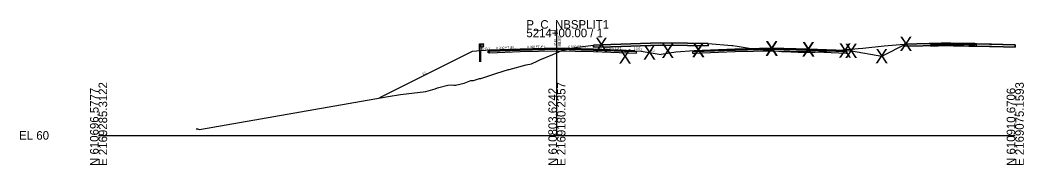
# Model space of a CAD drawing. Extents: x -26 to 1303, y -3010 to 12038.
# Drawn here: x 974.3 to 1302.8, y 7990.3 to 8037.8 of the extents above; entities that cross this region are included whole.
import ezdxf

# ---------------------------------------------------------------- set-up
doc = ezdxf.new("R2010")
doc.units = 0
for name, color, linetype in [('RD_GPK_XS_Cell', 7, 'Continuous'), ('RD_GPK_XS_Text_Node', 7, 'Continuous'), ('RD_PD_Final_TrvlWay', 7, 'Continuous'), ('RD_XS_Base', 7, 'Continuous'), ('RD_XS_ExGround', 7, 'Continuous'), ('RD_XS_ExPaveRet', 7, 'Continuous'), ('RD_XS_GR', 7, 'Continuous'), ('RD_XS_Greenside', 7, 'Continuous'), ('RD_XS_Pave', 7, 'Continuous'), ('RD_XS_PaveOvlay_CP', 7, 'Continuous'), ('RD_XS_TieSlope', 7, 'Continuous'), ('RD_XS_TX_Elev_EX', 7, 'Continuous'), ('RD_XS_TX_Elev_PR', 7, 'Continuous'), ('RD_XS_TX_ShdSlope', 7, 'Continuous'), ('RD_XS_TX_Slope', 7, 'Continuous')]:
    doc.layers.add(name, color=color, linetype=linetype)

msp = doc.modelspace()

# ---------------------------------------------------------------- linework, layer by layer
at = {"layer": 'RD_GPK_XS_Cell'}
for p, q in [((1150, 8000), (1150, 8035)), ((1000, 8000), (1150, 8000)), ((1150, 8000), (1300, 8000))]:
    msp.add_line(p, q, dxfattribs=at)
at = {"layer": 'RD_PD_Final_TrvlWay'}
for p, q in [((1125.11, 8027.7), (1124.61, 8027.66)), ((1124.61, 8027.66), (1124.61, 8024.09)), ((1125.11, 8024.09), (1125.11, 8027.7))]:
    msp.add_line(p, q, dxfattribs=at)
at = {"layer": 'RD_XS_Base'}
for p, q in [((1272.3, 8029.77), (1272.8, 8029.78)), ((1272.3, 8029.27), (1272.3, 8029.77)), ((1272.8, 8029.78), (1274.81, 8029.82)), ((1274.81, 8029.82), (1279.81, 8029.92)), ((1279.81, 8029.42), (1274.81, 8029.32)), ((1279.81, 8029.98), (1279.81, 8030.08)), ((1279.81, 8030.08), (1279.81, 8029.83)), ((1279.81, 8029.92), (1279.81, 8029.98)), ((1281.66, 8029.88), (1279.81, 8029.92)), ((1279.81, 8029.92), (1279.81, 8029.42)), ((1279.81, 8029.83), (1279.81, 8029.42)), ((1279.81, 8029.42), (1281.66, 8029.38)), ((1284.81, 8029.82), (1281.66, 8029.88)), ((1281.66, 8029.38), (1284.81, 8029.32)), ((1285.53, 8029.8), (1284.81, 8029.82)), ((1286.81, 8029.78), (1285.53, 8029.8)), ((1286.99, 8029.77), (1286.81, 8029.78)), ((1287.31, 8029.77), (1286.99, 8029.77)), ((1287.31, 8029.59), (1287.31, 8029.77)), ((1287.31, 8029.27), (1287.31, 8029.59)), ((1127.5, 8027.59), (1128, 8027.61)), ((1127.5, 8027.09), (1127.5, 8027.59)), ((1127.5, 8027.59), (1127.5, 8027.59)), ((1128, 8027.11), (1127.5, 8027.09)), ((1127.5, 8027.09), (1127.5, 8027.09)), ((1127.5, 8027.09), (1127.5, 8027.09)), ((1138, 8028.01), (1128, 8027.61)), ((1128, 8027.61), (1128, 8027.61)), ((1128, 8027.11), (1138, 8027.51)), ((1128, 8027.11), (1128, 8027.11)), ((1150, 8028.25), (1138, 8028.01)), ((1138, 8028.01), (1138, 8028.01)), ((1138, 8027.51), (1150, 8027.75)), ((1138, 8027.51), (1138, 8027.51)), ((1150, 8028.25), (1150, 8028.41)), ((1150, 8028.41), (1150, 8028.41)), ((1150, 8028.41), (1150, 8028.41)), ((1150, 8028.41), (1150, 8027.75)), ((1150, 8027.75), (1150, 8028.25)), ((1150, 8028.25), (1150, 8028.25)), ((1150, 8028.25), (1150, 8028.25)), ((1150, 8028.25), (1150, 8028.25)), ((1162, 8028.01), (1150, 8028.25)), ((1150, 8027.75), (1150, 8027.75)), ((1150, 8027.75), (1150, 8027.75)), ((1150, 8027.75), (1162, 8027.51)), ((1175.55, 8027.47), (1162, 8028.01)), ((1162, 8027.51), (1176.05, 8026.95)), ((1164, 8027.93), (1164, 8027.93)), ((1164, 8027.43), (1164, 8027.43)), ((1176.05, 8027.45), (1175.55, 8027.47)), ((1175.55, 8027.47), (1175.55, 8027.47)), ((1176.05, 8026.95), (1176.05, 8027.45)), ((1176.05, 8027.45), (1176.05, 8027.45)), ((1194.9, 8027.48), (1194.4, 8027.46)), ((1194.4, 8027.46), (1194.4, 8027.46)), ((1194.4, 8027.46), (1194.4, 8026.96)), ((1194.4, 8026.96), (1194.9, 8026.98)), ((1194.4, 8026.96), (1194.4, 8026.96)), ((1194.4, 8026.96), (1194.4, 8026.96)), ((1208.27, 8028.01), (1194.9, 8027.48)), ((1194.9, 8026.98), (1208.27, 8027.51)), ((1194.93, 8027.48), (1194.9, 8027.48)), ((1194.9, 8026.98), (1194.93, 8026.98)), ((1208.36, 8028.01), (1208.27, 8028.01)), ((1208.27, 8027.51), (1208.36, 8027.51)), ((1220.36, 8028.25), (1208.36, 8028.01)), ((1208.36, 8027.51), (1220.36, 8027.75)), ((1220.36, 8028.25), (1220.36, 8028.41)), ((1220.36, 8028.41), (1220.36, 8027.76)), ((1220.36, 8027.75), (1220.36, 8028.25)), ((1220.36, 8028.25), (1220.36, 8028.25)), ((1220.36, 8028.25), (1220.36, 8028.25)), ((1232.28, 8028.01), (1220.36, 8028.25)), ((1220.36, 8028.25), (1220.36, 8028.25)), ((1220.36, 8027.76), (1220.36, 8027.75)), ((1220.36, 8027.75), (1220.36, 8027.75)), ((1220.36, 8027.75), (1232.28, 8027.51)), ((1232.36, 8028.01), (1232.28, 8028.01)), ((1232.28, 8027.51), (1232.36, 8027.51)), ((1244.27, 8027.54), (1232.36, 8028.01)), ((1232.36, 8027.51), (1244.76, 8027.02)), ((1244.36, 8027.53), (1244.27, 8027.54)), ((1244.86, 8027.51), (1244.36, 8027.53)), ((1244.76, 8027.02), (1244.86, 8027.01)), ((1244.86, 8027.02), (1244.86, 8027.51)), ((1244.86, 8027.51), (1244.86, 8027.51)), ((1244.86, 8027.01), (1244.86, 8027.02)), ((1272.8, 8029.28), (1272.3, 8029.27)), ((1274.81, 8029.32), (1272.8, 8029.28)), ((1284.81, 8029.32), (1285.71, 8029.3)), ((1285.71, 8029.3), (1287.31, 8029.27))]:
    msp.add_line(p, q, dxfattribs=at)
at = {"layer": 'RD_XS_ExGround'}
msp.add_lwpolyline([(1031.91, 8002.12), (1032.33, 8002.12), (1033.07, 8001.92), (1094.8, 8012.79), (1098.76, 8013.47), (1107.09, 8014.38), (1110.17, 8015.26), (1110.96, 8015.57), (1114.35, 8016.51), (1115.54, 8016.57), (1116.29, 8016.51), (1116.83, 8016.47), (1119.67, 8017.18), (1121.83, 8018.02), (1122.67, 8018.01), (1124.65, 8018.63), (1125.12, 8018.66), (1130.36, 8020.45), (1134.15, 8021.57), (1134.18, 8021.58), (1134.2, 8021.58), (1134.37, 8021.63), (1139.93, 8023.19), (1141.71, 8023.52), (1143.58, 8024.4), (1144.42, 8024.79), (1148.61, 8026.5), (1151.61, 8027.86), (1156.64, 8028.98), (1161.99, 8029.65), (1167.6, 8029.84), (1183.9, 8030.39), (1192.72, 8030.24), (1199.5, 8030.11), (1207.23, 8029.53), (1207.57, 8029.5), (1209.03, 8029.28), (1213.59, 8028.52), (1217.46, 8028.12), (1222.49, 8027.64), (1223.49, 8027.53), (1224.26, 8027.49), (1228.91, 8027.34), (1233.06, 8027.15), (1247.46, 8028.41), (1248.58, 8028.5), (1250.13, 8028.66), (1257.05, 8029.33), (1263.62, 8029.98), (1275.72, 8030.21), (1278.6, 8030.26), (1291.59, 8029.91), (1300, 8029.67)], dxfattribs=at)
at = {"layer": 'RD_XS_ExPaveRet'}
for p, q in [((1167.6, 8029.84), (1161.99, 8029.65)), ((1183.9, 8030.39), (1167.6, 8029.84)), ((1192.72, 8030.24), (1183.9, 8030.39)), ((1278.93, 8030.26), (1278.6, 8030.26)), ((1300, 8029.67), (1300, 8028.92)), ((1300, 8028.92), (1300, 8029.67))]:
    msp.add_line(p, q, dxfattribs=at)
for points in [[(1199.5, 8030.11), (1199.5, 8029.36), (1199.5, 8029.36), (1199.5, 8029.36), (1192.72, 8029.49), (1192.72, 8029.49), (1183.9, 8029.64), (1183.9, 8029.64), (1183.9, 8029.64), (1167.6, 8029.09), (1167.6, 8029.09), (1161.99, 8028.9), (1161.99, 8028.9), (1161.99, 8028.9), (1161.99, 8029.65), (1161.99, 8029.65), (1167.6, 8029.84), (1167.6, 8029.84), (1183.9, 8030.39), (1183.9, 8030.39), (1183.9, 8030.39), (1192.72, 8030.24), (1192.72, 8030.24), (1199.5, 8030.11), (1199.5, 8030.11)], [(1161.99, 8029.65), (1161.99, 8028.9), (1167.6, 8029.09), (1183.9, 8029.64), (1192.72, 8029.49), (1199.5, 8029.36), (1199.5, 8029.36), (1199.5, 8030.11), (1199.5, 8030.11), (1192.72, 8030.24)], [(1300, 8028.92), (1292.21, 8029.14), (1291.59, 8029.16), (1278.93, 8029.51), (1278.6, 8029.51), (1275.98, 8029.46), (1275.72, 8029.46), (1263.89, 8029.23), (1263.62, 8029.23), (1263.62, 8029.23), (1263.62, 8029.23), (1263.62, 8029.25), (1263.62, 8029.98), (1263.62, 8029.98), (1263.62, 8029.98), (1263.89, 8029.98), (1275.72, 8030.21), (1275.98, 8030.21), (1278.6, 8030.26), (1278.93, 8030.26), (1291.59, 8029.91), (1292.21, 8029.89)], [(1278.6, 8030.26), (1275.98, 8030.21), (1275.72, 8030.21), (1263.89, 8029.98), (1263.62, 8029.98), (1263.62, 8029.98)], [(1263.62, 8029.98), (1263.62, 8029.25), (1263.62, 8029.23), (1263.62, 8029.23), (1263.89, 8029.23), (1275.72, 8029.46), (1275.98, 8029.46), (1278.6, 8029.51), (1278.93, 8029.51), (1291.59, 8029.16), (1292.21, 8029.14), (1300, 8028.92)], [(1300, 8029.67), (1292.21, 8029.89), (1291.59, 8029.91), (1278.93, 8030.26)], [(1292.21, 8029.89), (1300, 8029.67)]]:
    msp.add_lwpolyline(points, dxfattribs=at)
at = {"layer": 'RD_XS_GR'}
for points in [[(1125.11, 8030.09), (1125.11, 8027.7), (1124.61, 8027.66), (1124.61, 8030.09), (1124.86, 8030.09), (1125.11, 8030.09)], [(1125.77, 8030.09), (1125.77, 8028.93), (1125.11, 8028.93), (1125.11, 8030.09), (1125.77, 8030.09)], [(1126.04, 8029.8), (1125.77, 8030.09), (1125.77, 8028.93), (1125.77, 8028.93), (1125.77, 8028.93), (1126.04, 8029.22), (1126.04, 8029.22), (1125.77, 8029.51), (1125.77, 8029.51), (1126.04, 8029.8), (1126.04, 8029.8)]]:
    msp.add_lwpolyline(points, dxfattribs=at)
at = {"layer": 'RD_XS_Greenside'}
for p, q in [((1256.36, 8026.02), (1264.3, 8029.99)), ((1122.29, 8027.47), (1091.92, 8012.29)), ((1177.55, 8027.63), (1184.17, 8026.52)), ((1188.9, 8027.31), (1184.17, 8026.52)), ((1246.36, 8027.69), (1256.36, 8026.02))]:
    msp.add_line(p, q, dxfattribs=at)
at = {"layer": 'RD_XS_Pave'}
for p, q in [((1273.59, 8030.11), (1272.8, 8030.1)), ((1272.8, 8030.1), (1272.8, 8030)), ((1272.8, 8030), (1272.8, 8029.94)), ((1274.81, 8029.98), (1272.8, 8029.94)), ((1272.8, 8029.94), (1273.59, 8029.95)), ((1272.8, 8029.94), (1272.8, 8029.78)), ((1272.8, 8029.78), (1274.81, 8029.82)), ((1274.81, 8030.14), (1273.59, 8030.11)), ((1273.59, 8029.95), (1274.81, 8029.98)), ((1276.73, 8030.18), (1274.81, 8030.14)), ((1279.81, 8030.08), (1274.81, 8029.98)), ((1274.81, 8029.98), (1276.73, 8030.02)), ((1274.81, 8029.82), (1279.81, 8029.92)), ((1279.81, 8030.24), (1276.73, 8030.18)), ((1276.73, 8030.02), (1279.81, 8030.08)), ((1281.66, 8030.2), (1279.81, 8030.24)), ((1279.81, 8030.08), (1281.66, 8030.04)), ((1284.81, 8029.98), (1279.81, 8030.08)), ((1279.81, 8030.08), (1279.81, 8029.92)), ((1279.81, 8029.92), (1279.81, 8030.08)), ((1279.81, 8029.92), (1284.81, 8029.82)), ((1284.81, 8030.14), (1281.66, 8030.2)), ((1281.66, 8030.04), (1284.81, 8029.98)), ((1285.53, 8030.12), (1284.81, 8030.14)), ((1284.81, 8029.98), (1285.53, 8029.96)), ((1286.81, 8029.94), (1284.81, 8029.98)), ((1284.81, 8029.82), (1286.81, 8029.78)), ((1286.81, 8030.1), (1285.53, 8030.12)), ((1285.53, 8029.96), (1286.81, 8029.94)), ((1286.81, 8029.99), (1286.81, 8030.1)), ((1286.81, 8029.94), (1286.81, 8029.99)), ((1286.81, 8029.78), (1286.81, 8029.94)), ((1138, 8028.33), (1128, 8027.93)), ((1138, 8028.17), (1128, 8027.77)), ((1128, 8027.77), (1138, 8028.17)), ((1128, 8027.61), (1138, 8028.01)), ((1128, 8027.93), (1128, 8027.93)), ((1128, 8027.93), (1128, 8027.77)), ((1128, 8027.77), (1128, 8027.77)), ((1128, 8027.77), (1128, 8027.61)), ((1128, 8027.77), (1128, 8027.77)), ((1128, 8027.77), (1128, 8027.77)), ((1128, 8027.61), (1128, 8027.61)), ((1128, 8027.61), (1128, 8027.61)), ((1150, 8028.57), (1138, 8028.33)), ((1150, 8028.41), (1138, 8028.17)), ((1138, 8028.17), (1150, 8028.41)), ((1138, 8028.33), (1138, 8028.33)), ((1138, 8028.01), (1150, 8028.25)), ((1138, 8028.17), (1138, 8028.17)), ((1138, 8028.17), (1138, 8028.17)), ((1138, 8028.01), (1138, 8028.01)), ((1162, 8028.33), (1150, 8028.57)), ((1150, 8028.57), (1150, 8028.57)), ((1150, 8028.57), (1150, 8028.57)), ((1150, 8028.25), (1150, 8028.41)), ((1150, 8028.41), (1150, 8028.41)), ((1150, 8028.41), (1150, 8028.41)), ((1150, 8028.41), (1150, 8028.41)), ((1150, 8028.41), (1150, 8028.41)), ((1150, 8028.41), (1162, 8028.17)), ((1162, 8028.17), (1150, 8028.41)), ((1150, 8028.41), (1150, 8028.41)), ((1150, 8028.41), (1150, 8028.41)), ((1150, 8028.41), (1150, 8028.25)), ((1150, 8028.25), (1150, 8028.25)), ((1150, 8028.25), (1150, 8028.25)), ((1150, 8028.25), (1162, 8028.01)), ((1175.55, 8027.79), (1162, 8028.33)), ((1162, 8028.17), (1175.55, 8027.63)), ((1175.55, 8027.63), (1162, 8028.17)), ((1162, 8028.01), (1175.55, 8027.47)), ((1164, 8028.25), (1164, 8028.25)), ((1164, 8028.09), (1164, 8028.09)), ((1164, 8028.09), (1164, 8028.09)), ((1164, 8027.93), (1164, 8027.93)), ((1175.55, 8027.63), (1175.55, 8027.79)), ((1175.55, 8027.79), (1175.55, 8027.79)), ((1175.55, 8027.47), (1175.55, 8027.63)), ((1175.55, 8027.63), (1175.55, 8027.63)), ((1208.27, 8028.33), (1194.9, 8027.79)), ((1208.27, 8028.17), (1194.9, 8027.63)), ((1194.9, 8027.63), (1208.27, 8028.17)), ((1194.9, 8027.48), (1208.27, 8028.01)), ((1194.93, 8027.79), (1194.9, 8027.79)), ((1194.9, 8027.79), (1194.9, 8027.63)), ((1194.93, 8027.64), (1194.9, 8027.63)), ((1194.9, 8027.63), (1194.93, 8027.64)), ((1194.9, 8027.63), (1194.9, 8027.48)), ((1194.9, 8027.63), (1194.9, 8027.63)), ((1194.9, 8027.48), (1194.9, 8027.48)), ((1194.9, 8027.48), (1194.93, 8027.48)), ((1208.36, 8028.33), (1208.27, 8028.33)), ((1208.36, 8028.17), (1208.27, 8028.17)), ((1208.27, 8028.17), (1208.36, 8028.17)), ((1208.27, 8028.01), (1208.36, 8028.01)), ((1220.36, 8028.57), (1208.36, 8028.33)), ((1220.36, 8028.41), (1208.36, 8028.17)), ((1208.36, 8028.17), (1220.36, 8028.41)), ((1208.36, 8028.01), (1220.36, 8028.25)), ((1232.28, 8028.33), (1220.36, 8028.57)), ((1220.36, 8028.25), (1220.36, 8028.41)), ((1220.36, 8028.41), (1232.28, 8028.17)), ((1232.28, 8028.17), (1220.36, 8028.41)), ((1220.36, 8028.41), (1220.36, 8028.41)), ((1220.36, 8028.41), (1220.36, 8028.41)), ((1220.36, 8028.41), (1220.36, 8028.25)), ((1220.36, 8028.25), (1220.36, 8028.25)), ((1220.36, 8028.25), (1220.36, 8028.25)), ((1220.36, 8028.25), (1220.36, 8028.25)), ((1220.36, 8028.25), (1220.36, 8028.25)), ((1220.36, 8028.25), (1232.28, 8028.01)), ((1232.36, 8028.33), (1232.28, 8028.33)), ((1232.28, 8028.17), (1232.36, 8028.17)), ((1232.36, 8028.17), (1232.28, 8028.17)), ((1232.28, 8028.01), (1232.36, 8028.01)), ((1244.27, 8027.85), (1232.36, 8028.33)), ((1232.36, 8028.17), (1244.27, 8027.69)), ((1244.27, 8027.69), (1232.36, 8028.17)), ((1232.36, 8028.01), (1244.27, 8027.54)), ((1244.36, 8027.85), (1244.27, 8027.85)), ((1244.27, 8027.69), (1244.36, 8027.69)), ((1244.36, 8027.69), (1244.27, 8027.69)), ((1244.27, 8027.54), (1244.36, 8027.53)), ((1244.36, 8027.69), (1244.36, 8027.85)), ((1244.36, 8027.69), (1244.36, 8027.69)), ((1244.36, 8027.53), (1244.36, 8027.69)), ((1244.36, 8027.53), (1244.36, 8027.53))]:
    msp.add_line(p, q, dxfattribs=at)
at = {"layer": 'RD_XS_PaveOvlay_CP'}
for p, q in [((1272.8, 8030.1), (1274.81, 8030.14)), ((1274.81, 8030.14), (1279.81, 8030.24)), ((1279.81, 8030.24), (1284.81, 8030.14)), ((1284.81, 8030.14), (1286.81, 8030.1)), ((1128, 8027.93), (1138, 8028.33)), ((1138, 8028.33), (1150, 8028.57)), ((1150, 8028.57), (1162, 8028.33)), ((1162, 8028.33), (1175.55, 8027.79)), ((1208.27, 8028.33), (1194.9, 8027.79)), ((1194.93, 8027.79), (1194.9, 8027.79)), ((1208.36, 8028.33), (1208.27, 8028.33)), ((1220.36, 8028.57), (1208.36, 8028.33)), ((1232.28, 8028.33), (1220.36, 8028.57)), ((1232.36, 8028.33), (1232.28, 8028.33)), ((1244.27, 8027.85), (1232.36, 8028.33)), ((1244.36, 8027.85), (1244.27, 8027.85))]:
    msp.add_line(p, q, dxfattribs=at)
at = {"layer": 'RD_XS_TieSlope'}
for p, q in [((1128, 8027.93), (1122.29, 8027.47)), ((1175.55, 8027.79), (1177.55, 8027.63)), ((1194.9, 8027.79), (1188.9, 8027.31)), ((1244.36, 8027.85), (1246.36, 8027.69))]:
    msp.add_line(p, q, dxfattribs=at)

# ---------------------------------------------------------------- texts
at = {"layer": 'RD_GPK_XS_Cell'}
for s, p in [('P_C_NBSPLIT1', (1140, 8035)), ('5214+00.00 / 1', (1140, 8032.2)), ('EL 60', (974, 7998.6))]:
    msp.add_text(s, height=2.8, dxfattribs=at).set_placement(p)
for s, p in [('E 2169285.3122', (1002.8, 7990)), ('E 2169180.2357', (1152.8, 7990)), ('E 2169075.1593', (1302.8, 7990)), ('N 610696.5777', (1000, 7990)), ('N 610803.6242', (1150, 7990)), ('N 610910.6706', (1300, 7990))]:
    msp.add_text(s, height=2.8, rotation=90, dxfattribs=at).set_placement(p)
at = {"layer": 'RD_GPK_XS_Text_Node'}
for p in [(1162.46, 8027.4), (1178.2, 8024.87), (1184.2, 8025.35), (1194.2, 8025.75), (1194.2, 8025.59), (1218.2, 8026.23), (1218.2, 8026.07), (1230.2, 8025.99), (1230.2, 8025.83), (1242.2, 8025.51), (1244.2, 8025.35), (1262.13, 8027.65), (1170.2, 8023.53), (1254.2, 8023.68)]:
    msp.add_text('X', height=4.69, dxfattribs=at).set_placement(p)
at = {"layer": 'RD_XS_TX_Elev_EX'}
msp.add_text('87.13', height=0.6, rotation=90, dxfattribs=at).set_placement((1149.66, 8029.44))
at = {"layer": 'RD_XS_TX_Elev_PR'}
msp.add_text('88.57', height=1, rotation=90, dxfattribs=at).set_placement((1151.33, 8029.13))
at = {"layer": 'RD_XS_TX_ShdSlope'}
for rotation, p in [(4.5739, (1125.26, 8027.9)), (355.4261, (1175.17, 8028.13))]:
    msp.add_text('12.5:1', height=0.75, rotation=rotation, dxfattribs=at).set_placement(p)
at = {"layer": 'RD_XS_TX_Slope'}
for s, rotation, p in [('0.020 FT./FT.', 1.1458, (1140.25, 8028.61)), ('0.020 FT./FT.', 358.8542, (1153.79, 8028.73)), ('0.040 FT./FT.', 2.2906, (1130.22, 8028.28)), ('0.040 FT./FT.', 357.7094, (1165.26, 8028.43)), ('6:1', 350.5377, (1180.57, 8027.62)), ('2:1', 26.5651, (1106.13, 8019.74))]:
    msp.add_text(s, height=0.75, rotation=rotation, dxfattribs=at).set_placement(p)

doc.saveas('drawing.dxf')
